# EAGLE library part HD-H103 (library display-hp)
LED DISPLAY 1-character 7 segment, decimal point right
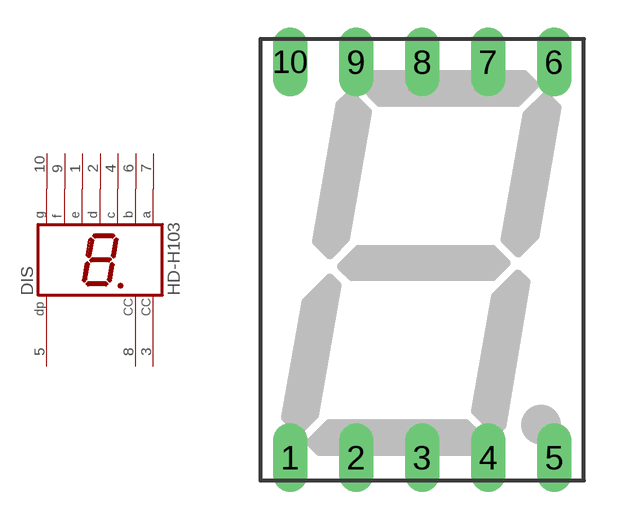
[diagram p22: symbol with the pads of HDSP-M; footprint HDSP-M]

Designator prefix DIS

## HD-H103 (OC_FARNELL: unknown; OC_NEWARK: unknown)  [HDSP-M]
1  E  pas
2  D  pas
3  CC  pas
4  C  pas
5  DP  pas
6  B  pas
7  A  pas
8  CC  pas
9  F  pas
10  G  pas

## Footprint HDSP-M (pad centres in mm)
LED DISPLAY 15-mm 1 character 7 segment, decimal point right
drill 0.813 long: 1 -5.08,-7.62; 2 -2.54,-7.62; 3 0,-7.62; 4 2.54,-7.62; 5 5.08,-7.62; 6 5.08,7.62; 7 2.54,7.62; 8 0,7.62; 9 -2.54,7.62; 10 -5.08,7.62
